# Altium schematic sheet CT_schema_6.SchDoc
size 405 x 220 mm
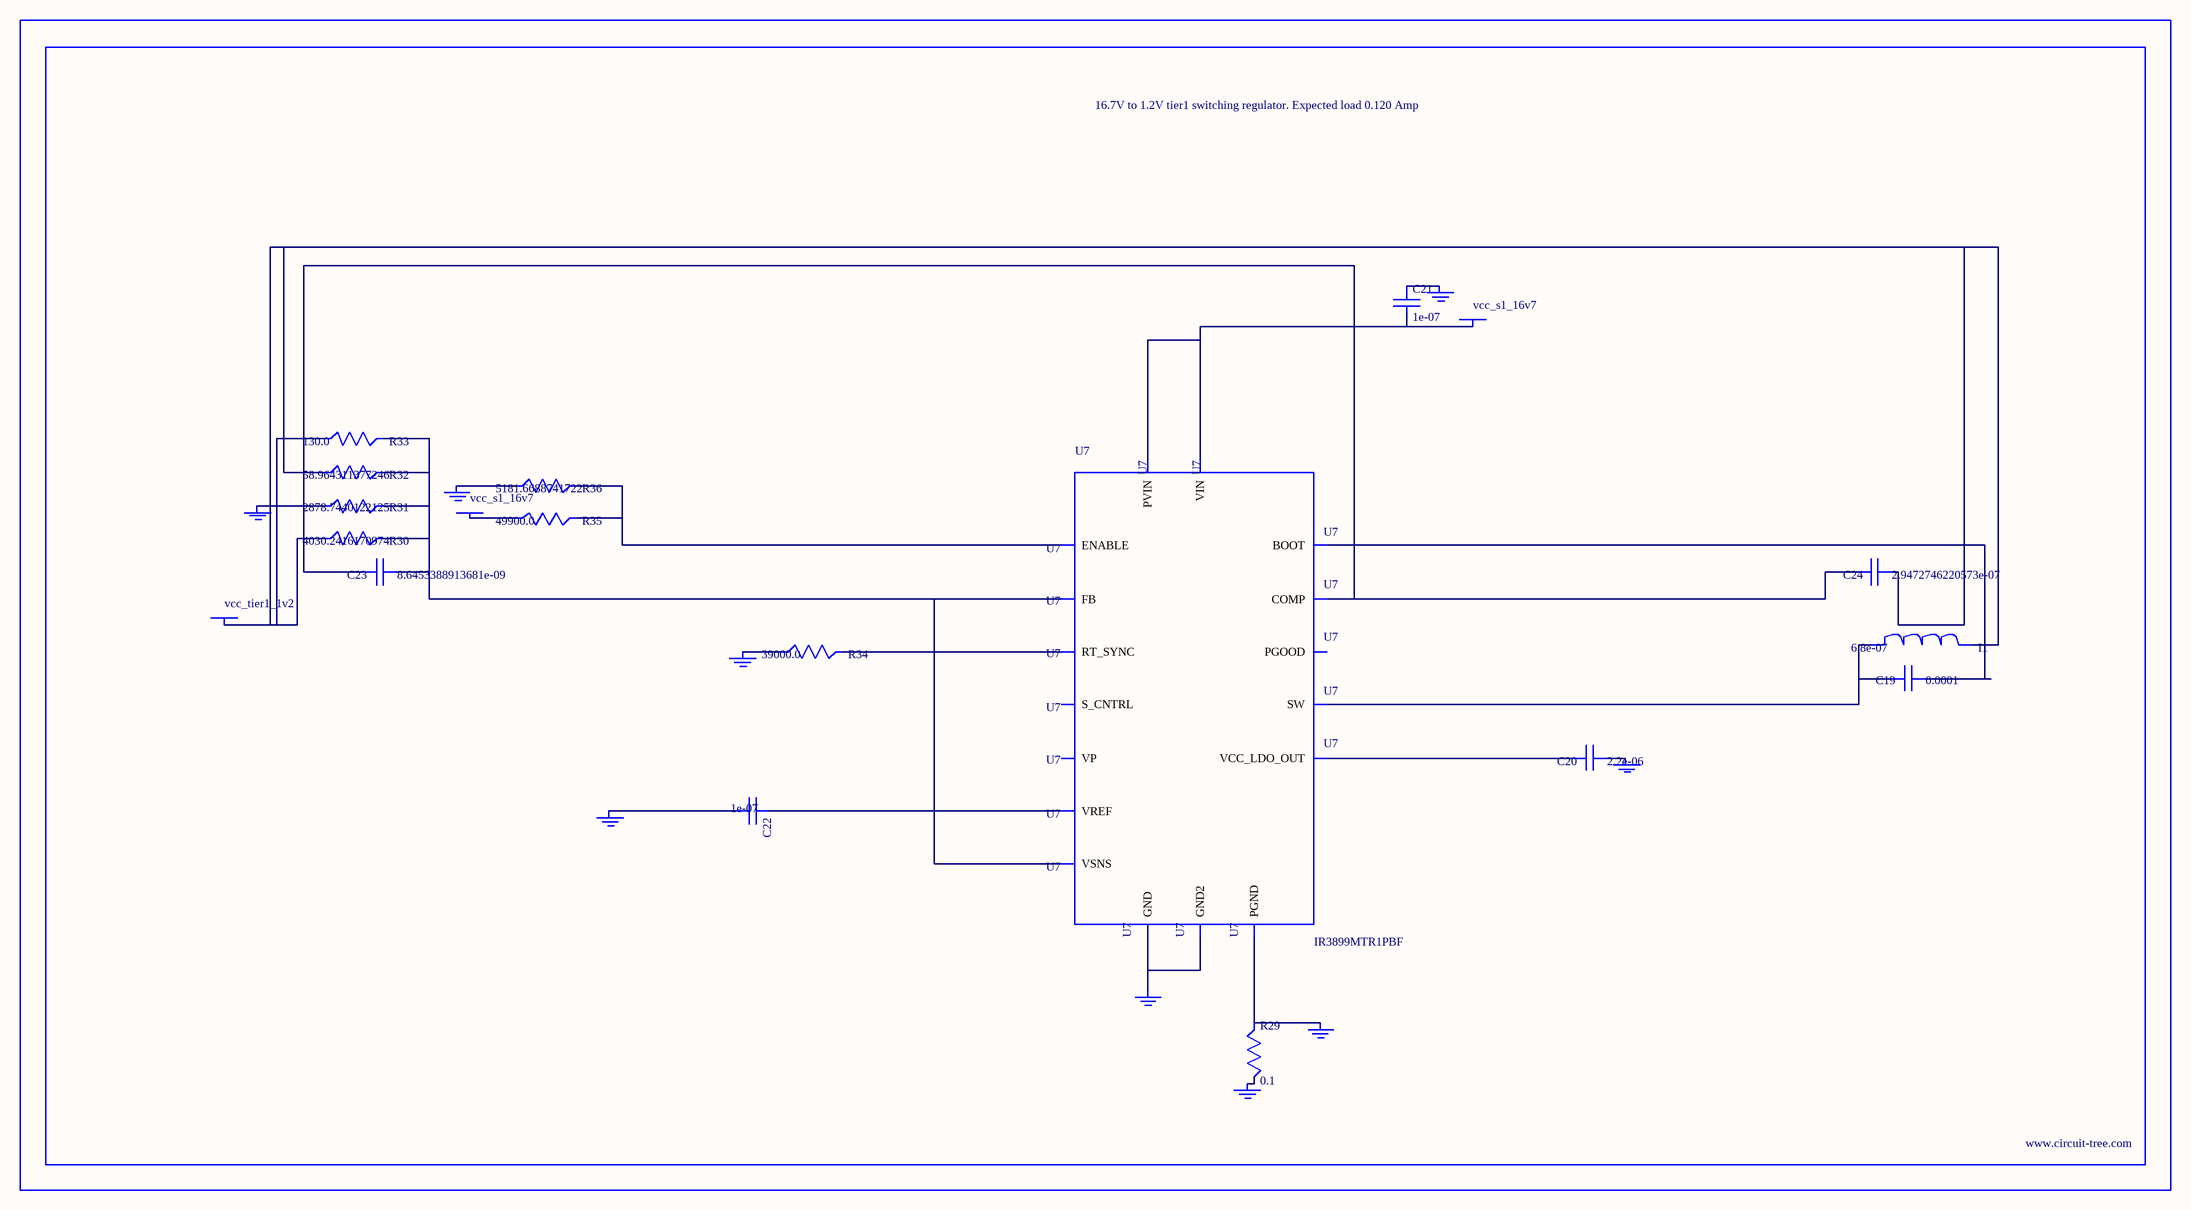
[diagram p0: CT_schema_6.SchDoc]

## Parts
BORDER5  (no value)
C19  0.0001  [C1210]
C20  2.2e-06  [C0603]
C21  1e-07  [C0402]
C22  1e-07  [C0402]
C23  8.6453388913681e-09  [R0603]
C24  2.9472746220573e-07  [R0603]
GND_INSTANCE_5_0  (no value)
GND_INSTANCE_5_1  (no value)
GND_INSTANCE_5_2  (no value)
GND_INSTANCE_5_3  (no value)
GND_INSTANCE_5_4  (no value)
GND_INSTANCE_5_5  (no value)
GND_INSTANCE_5_6  (no value)
GND_INSTANCE_5_7  (no value)
GND_INSTANCE_5_8  (no value)
I1  6.8e-07  [IND25X25CZ]
POWER_INSTANCE_5_0  vcc_s1_16v7
POWER_INSTANCE_5_1  vcc_s1_16v7
POWER_INSTANCE_5_2  vcc_tier1_1v2
R29  0.1  [R0603]
R30  4030.2416170974  [R0603]
R31  2878.7440122125  [R0603]
R32  58.964311377246  [R0603]
R33  130.0  [R0603]
R34  39000.0  [R0603]
R35  49900.0  [R0603]
R36  5181.6688741722  [R0603]
U7  IR3899MTR1PBF  [IR3899MTR1PBF]

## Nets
NetC19_1: C19.1 U7.14(BOOT)
NetC19_2: C19.2 I1.1 U7.12(SW)
NetC20_1: C20.1 GND_INSTANCE_5_4.0(GND)
NetC20_2: C20.2 U7.10(VCC_LDO_OUT)
NetC21_1: C21.1 GND_INSTANCE_5_3.0(GND)
NetC21_2: C21.2 POWER_INSTANCE_5_0.0(PWR) U7.9(VIN) U7.13(PVIN)
NetC22_1: C22.1 U7.2(VREF)
NetC22_2: C22.2 GND_INSTANCE_5_1.0(GND)
NetC23_1: C23.1 R30.2 R31.2 R32.2 R33.2 U7.1(FB) U7.8(VSNS)
NetC23_2: C23.2 C24.2 U7.3(COMP)
NetC24_1: C24.1 I1.2 POWER_INSTANCE_5_2.0(PWR) R30.1 R32.1 R33.1
NetGND_INSTANCE_5_0_0: GND_INSTANCE_5_0.0(GND) R31.1
NetGND_INSTANCE_5_2_0: GND_INSTANCE_5_2.0(GND) R34.1
NetGND_INSTANCE_5_5_0: GND_INSTANCE_5_5.0(GND) R29.2
NetGND_INSTANCE_5_6_0: GND_INSTANCE_5_6.0(GND) R29.1 U7.11(PGND)
NetGND_INSTANCE_5_7_0: GND_INSTANCE_5_7.0(GND) R36.1
NetGND_INSTANCE_5_8_0: GND_INSTANCE_5_8.0(GND) U7.4(GND) U7.17(GND2)
NetPOWER_INSTANCE_5_1_0: POWER_INSTANCE_5_1.0(PWR) R35.1
NetR34_2: R34.2 U7.5(RT_SYNC)
NetR35_2: R35.2 R36.2 U7.15(ENABLE)

Not connected (* = marked no-connect by the designer): U7 6(S_CNTRL) 7(PGOOD) 16(VP)

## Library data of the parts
BORDER5 = BORDER_PAGE5
C19 = GRM32ER61A107ME20L
C20 = C0603C225K8RACTU
C21 C22 = C0402C104K3RACTU
C23 = C23
C24 = C24
GND_INSTANCE_5_0-GND_INSTANCE_5_8 = GND
I1 = IHLP2525CZERR68M01
POWER_INSTANCE_5_0-POWER_INSTANCE_5_2 = PWR
R29 = ERJ-3RSFR10V
R30 = R30
R31 = R31
R32 = R32
R33 = RC0603JR-07130RL
R34 = RC0603JR-0739KL
R35 = RC0603FR-0749K9
R36 = R36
